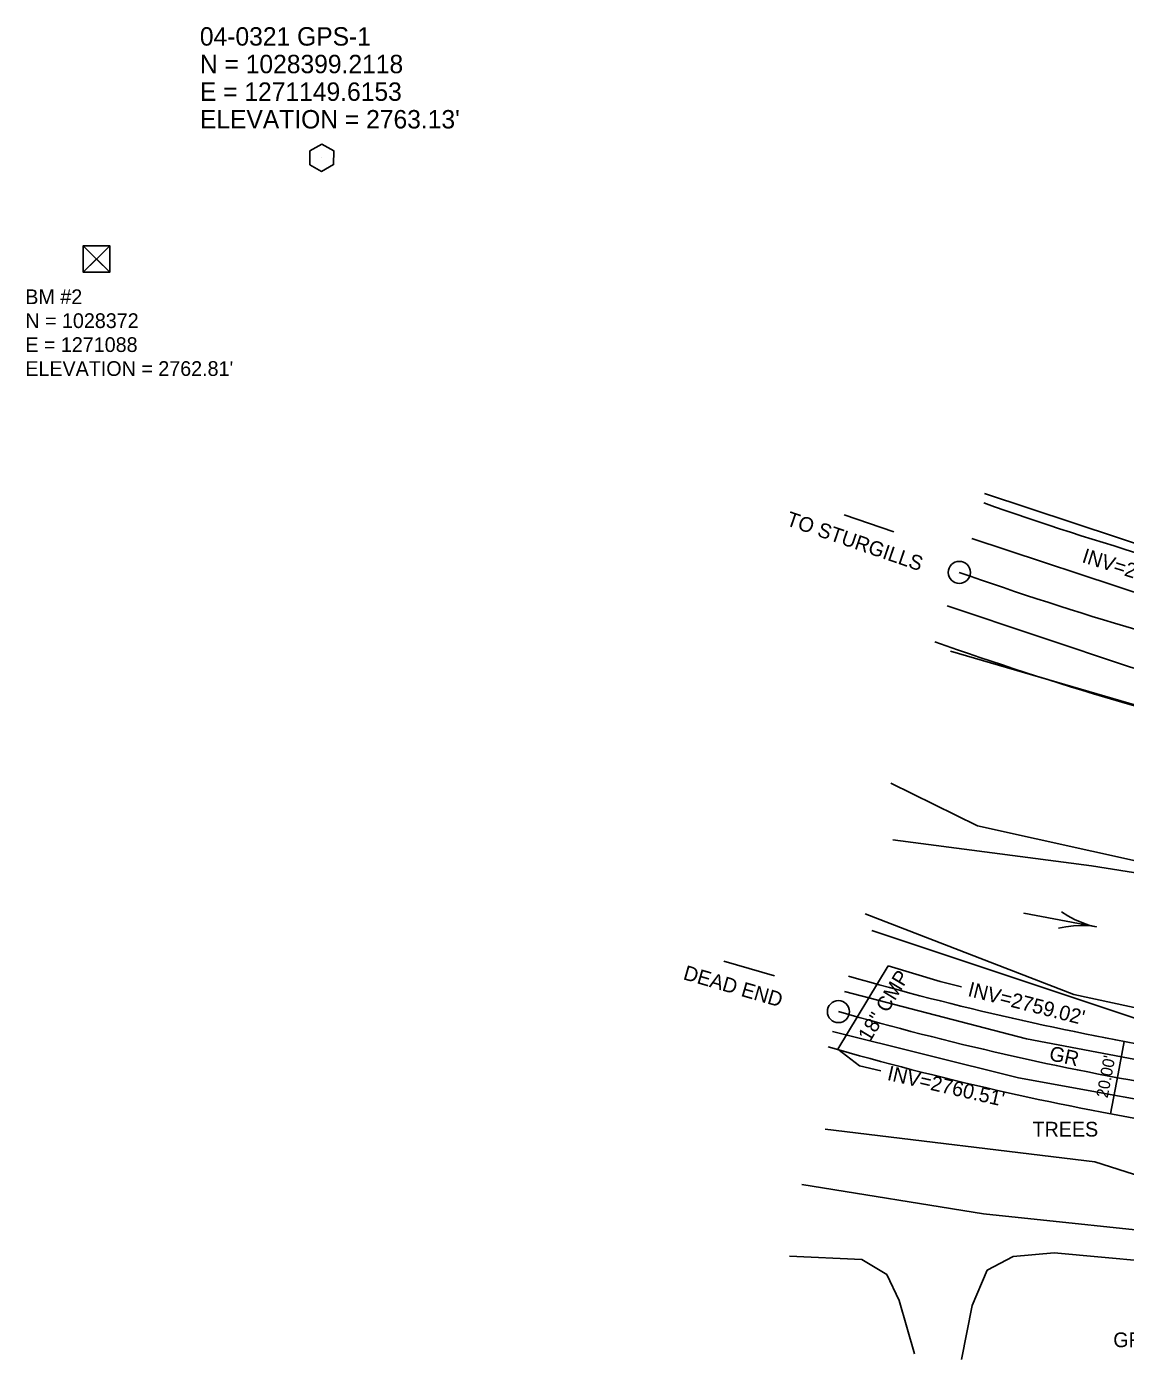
# Model space of a CAD drawing. Extents: x 1271070 to 1271913, y 1027587 to 1028435.
# Drawn here: x 1271069.6 to 1271367.8, y 1028069.2 to 1028434.7 of the extents above; entities that cross this region are included whole.
import ezdxf

# ---------------------------------------------------------------- set-up
doc = ezdxf.new("R2010")
doc.units = 0
for name, color, linetype in [('CTL Primary Horizontal and Vertical CELL', 7, 'Continuous'), ('CTL Primary Horizontal and Vertical Text', 7, 'Continuous'), ('CTL Vertical Benchmark CELL', 7, 'Continuous'), ('CTL Vertical Benchmark Text', 7, 'Continuous'), ('Exist Horizontal Alignment', 7, 'Continuous'), ('Exist Horizontal Alignment Point', 7, 'Continuous'), ('Exist Hydro Jurisdictional Stream or Body of Water', 7, 'Continuous'), ('Exist Hydro River Flow Arrow CELL', 7, 'Continuous'), ('Exist Other Culture Fence Line', 7, 'Continuous'), ('Exist Right of Way Line', 7, 'Continuous'), ('Exist Right of Way Width CELL', 7, 'Continuous'), ('Exist Roads EOP', 7, 'Continuous'), ('Exist Roads EOP Leader', 7, 'Continuous'), ('Exist Roads EOP Text', 7, 'Continuous'), ('Exist Roads Soil', 7, 'Continuous'), ('Exist Roads Soil Leader', 7, 'Continuous'), ('Exist Roads Soil Text', 7, 'Continuous'), ('Exist Structure Minor Pipes CMP 18 Inch', 7, 'Continuous'), ('Exist Structure Minor Pipes CMP 18 Inch Invert', 7, 'Continuous'), ('Exist Structure Minor Pipes CMP 18 Inch Leader', 7, 'Continuous'), ('Exist Structure Minor Pipes CMP 18 Inch Text', 7, 'Continuous'), ('Exist Vegetation Woods Line', 7, 'Continuous'), ('Exist Vegetation Woods Line Text', 7, 'Continuous')]:
    doc.layers.add(name, color=color, linetype=linetype)

msp = doc.modelspace()

# ---------------------------------------------------------------- linework, layer by layer
at = {"layer": 'CTL Primary Horizontal and Vertical CELL'}
msp.add_line((1271149.62, 1028399.21), (1271149.62, 1028399.21), dxfattribs=at)
msp.add_lwpolyline([(1271146.38, 1028401.08), (1271149.63, 1028402.9), (1271152.88, 1028401.11), (1271152.83, 1028397.38), (1271149.58, 1028395.5), (1271146.38, 1028397.31)], close=True, dxfattribs=at)
at = {"layer": 'CTL Vertical Benchmark CELL'}
msp.add_line((1271088.46, 1028371.72), (1271088.46, 1028371.72), dxfattribs=at)
msp.add_lwpolyline([(1271084.86, 1028375.3), (1271092.05, 1028375.3), (1271092.05, 1028368.12), (1271084.86, 1028368.12)], close=True, dxfattribs=at)
for points in [[(1271092.05, 1028375.3), (1271084.86, 1028368.12), (1271088.46, 1028371.71), (1271092.05, 1028368.12), (1271084.86, 1028375.3)], [(1271088.46, 1028371.71), (1271092.05, 1028375.3), (1271084.86, 1028375.3), (1271088.46, 1028371.71)], [(1271088.46, 1028371.71), (1271084.86, 1028368.12), (1271092.05, 1028368.12), (1271088.46, 1028371.71)]]:
    msp.add_lwpolyline(points, dxfattribs=at)
at = {"layer": 'Exist Horizontal Alignment'}
for centre, radius, start, end in [((1271654.06, 1029230.12), 1000, 250.65216, 256.46543), ((1271520.23, 1028970.58), 835.59, 254.00259, 260.37659)]:
    msp.add_arc(centre, radius, start, end, dxfattribs=at)
at = {"layer": 'Exist Horizontal Alignment Point'}
for centre in [(1271322.76, 1028286.6), (1271289.95, 1028167.35)]:
    msp.add_circle(centre, 3, dxfattribs=at)
at = {"layer": 'Exist Hydro Jurisdictional Stream or Body of Water'}
for points in [[(1271304.7, 1028214.03), (1271358.66, 1028206.9), (1271411.07, 1028198.58), (1271456, 1028198.43), (1271510.08, 1028186.94), (1271560.93, 1028171.69), (1271591.08, 1028158.12), (1271592.88, 1028151.16), (1271591.46, 1028148.01), (1271611.09, 1028139.56), (1271653.5, 1028127.81), (1271692.8, 1028106.61), (1271731.61, 1028109.95), (1271774.25, 1028123.55), (1271810.26, 1028145.38)], [(1271297.21, 1028193.87), (1271353.83, 1028172.03), (1271400.51, 1028161.95), (1271458.18, 1028160.15), (1271502.92, 1028146.33), (1271550.98, 1028136.88), (1271578, 1028118.14), (1271596.52, 1028108.85), (1271635.13, 1028092.8), (1271673.17, 1028073.83), (1271694.14, 1028069.18), (1271732.54, 1028081.77), (1271795.86, 1028101.38), (1271818.57, 1028109)]]:
    msp.add_lwpolyline(points, dxfattribs=at)
at = {"layer": 'Exist Hydro River Flow Arrow CELL'}
msp.add_line((1271350.13, 1028192.22), (1271350.13, 1028192.22), dxfattribs=at)
msp.add_lwpolyline([(1271350.55, 1028194.47), (1271352.26, 1028193.35), (1271354.08, 1028192.36), (1271356, 1028191.52), (1271357.95, 1028190.83), (1271359.96, 1028190.38), (1271340.3, 1028194.06), (1271359.96, 1028190.38), (1271357.93, 1028190.69), (1271355.85, 1028190.75), (1271353.76, 1028190.66), (1271351.71, 1028190.4), (1271349.71, 1028189.97)], dxfattribs=at)
at = {"layer": 'Exist Other Culture Fence Line'}
msp.add_lwpolyline([(1271329.58, 1028308.04), (1271377.99, 1028292.04), (1271424.8, 1028279.04), (1271475.06, 1028267.76), (1271522.2, 1028258.62), (1271572.4, 1028250.75), (1271617.37, 1028243.97), (1271662.13, 1028238.98), (1271711.39, 1028235.36)], dxfattribs=at)
at = {"layer": 'Exist Right of Way Line'}
for centre, radius, start, end in [((1271654.06, 1029230.12), 980, 250.65216, 256.46543), ((1271654.06, 1029230.12), 1020, 250.65216, 256.46543), ((1271520.23, 1028970.58), 825.59, 254.00259, 260.37659), ((1271520.23, 1028970.58), 845.59, 254.00259, 260.37659)]:
    msp.add_arc(centre, radius, start, end, dxfattribs=at)
at = {"layer": 'Exist Right of Way Width CELL'}
for p in [(1271367.51, 1028159.24), (1271363.81, 1028139.58)]:
    msp.add_line(p, (1271365.86, 1028150.48), dxfattribs=at)
at = {"layer": 'Exist Roads EOP'}
for points in [[(1271326.12, 1028295.81), (1271374.93, 1028279.7), (1271422.05, 1028266.63), (1271472.3, 1028255.59), (1271520.64, 1028246.3), (1271571.03, 1028237.98), (1271615.64, 1028231.31), (1271659.72, 1028225.08), (1271708.96, 1028218.32), (1271759.42, 1028212.65), (1271812.87, 1028207.39)], [(1271319.45, 1028277.54), (1271369.22, 1028260.92), (1271417.71, 1028247.94), (1271468.48, 1028236.99), (1271517.72, 1028227.81), (1271568.11, 1028219.26), (1271595.03, 1028215.07), (1271602.11, 1028209.33), (1271606.99, 1028200.81), (1271609.21, 1028190.89), (1271609.19, 1028179.92), (1271606.63, 1028171.4)]]:
    msp.add_lwpolyline(points, dxfattribs=at)
at = {"layer": 'Exist Roads EOP Leader'}
msp.add_lwpolyline([(1271291.47, 1028302.26), (1271305.01, 1028297.61)], dxfattribs=at)
at = {"layer": 'Exist Roads Soil'}
for points in [[(1271396.41, 1028149.48), (1271341.01, 1028159.96), (1271291.55, 1028172.76)], [(1271394.68, 1028139.2), (1271338.88, 1028149.38), (1271288.34, 1028161.93)], [(1271387.72, 1028106.24), (1271329.37, 1028112.44), (1271279.97, 1028120.41)], [(1271386.06, 1028098.42), (1271348.48, 1028101.85), (1271337.38, 1028100.86), (1271330.35, 1028097.09), (1271326.29, 1028087.54), (1271323.35, 1028072.9)], [(1271276.69, 1028100.92), (1271296.26, 1028100.04), (1271303.04, 1028095.98), (1271306.46, 1028088.88), (1271310.55, 1028074.4)]]:
    msp.add_lwpolyline(points, dxfattribs=at)
at = {"layer": 'Exist Roads Soil Leader'}
msp.add_lwpolyline([(1271258.82, 1028181.06), (1271272.57, 1028177.1)], dxfattribs=at)
at = {"layer": 'Exist Structure Minor Pipes CMP 18 Inch'}
msp.add_line((1271289.76, 1028157.11), (1271303.45, 1028179.8), dxfattribs=at)
at = {"layer": 'Exist Structure Minor Pipes CMP 18 Inch Leader'}
for points in [[(1271303.45, 1028179.8), (1271317.57, 1028175.52), (1271323.39, 1028174.05)], [(1271289.76, 1028157.11), (1271295.62, 1028152.57), (1271301.47, 1028151.22)]]:
    msp.add_lwpolyline(points, dxfattribs=at)
at = {"layer": 'Exist Vegetation Woods Line'}
for points in [[(1271320.34, 1028265.26), (1271388.96, 1028245.21), (1271486.11, 1028222.06), (1271555.88, 1028208.95), (1271583.64, 1028180.02), (1271579.16, 1028169.47), (1271530.83, 1028180.79), (1271472.23, 1028197.76), (1271434.45, 1028197.76), (1271374.7, 1028207.41), (1271327.66, 1028217.82), (1271304.15, 1028229.39)], [(1271299.01, 1028189.41), (1271370.71, 1028165.49), (1271422.37, 1028158.55), (1271482.51, 1028151.61), (1271457.84, 1028101.47), (1271408.11, 1028111.11), (1271359.53, 1028126.54), (1271286.29, 1028135.41)]]:
    msp.add_lwpolyline(points, dxfattribs=at)

# ---------------------------------------------------------------- texts
at = {"layer": 'CTL Primary Horizontal and Vertical Text'}
for s, p in [('04-0321 GPS-1', (1271116.52, 1028429.67)), ('N = 1028399.2118', (1271116.52, 1028422.17)), ('E = 1271149.6153', (1271116.52, 1028414.67)), ("ELEVATION = 2763.13'", (1271116.52, 1028407.17))]:
    msp.add_text(s, height=5, dxfattribs=at).set_placement(p)
at = {"layer": 'CTL Vertical Benchmark Text'}
for s, p in [('BM #2', (1271069.11, 1028359.47)), ('N = 1028372', (1271069.11, 1028352.97)), ('E = 1271088', (1271069.11, 1028346.47)), ("ELEVATION = 2762.81'", (1271069.11, 1028339.97))]:
    msp.add_text(s, height=4, dxfattribs=at).set_placement(p)
at = {"layer": 'Exist Right of Way Width CELL'}
msp.add_text("20.00'", height=3.2, rotation=79.34, dxfattribs=at).set_placement((1271363.04, 1028143.73))
at = {"layer": 'Exist Roads EOP Text'}
msp.add_text('TO STURGILLS', height=4, rotation=341.012, dxfattribs=at).set_placement((1271275.49, 1028299.48))
at = {"layer": 'Exist Roads Soil Text'}
for s, rotation, p in [('DEAD END', 343.9013, (1271247.54, 1028176.16)), ('GR', 347.4705, (1271346.93, 1028154.2))]:
    msp.add_text(s, height=4, rotation=rotation, dxfattribs=at).set_placement(p)
at = {"layer": 'Exist Structure Minor Pipes CMP 18 Inch Invert'}
for s, rotation, p in [("INV=2755.80'", 342.4667, (1271355.84, 1028289.44)), ("INV=2759.02'", 345.795, (1271324.84, 1028171.62)), ("INV=2760.51'", 346.9995, (1271302.97, 1028148.82))]:
    msp.add_text(s, height=4, rotation=rotation, dxfattribs=at).set_placement(p)
at = {"layer": 'Exist Structure Minor Pipes CMP 18 Inch Text'}
msp.add_text('18" CMP', height=4, rotation=58.9012, dxfattribs=at).set_placement((1271298.44, 1028158.81))
at = {"layer": 'Exist Vegetation Woods Line Text'}
for s, p in [('TREES', (1271342.65, 1028133.41)), ('GRASS', (1271364.57, 1028076.21))]:
    msp.add_text(s, height=4, dxfattribs=at).set_placement(p)

doc.saveas('drawing.dxf')
